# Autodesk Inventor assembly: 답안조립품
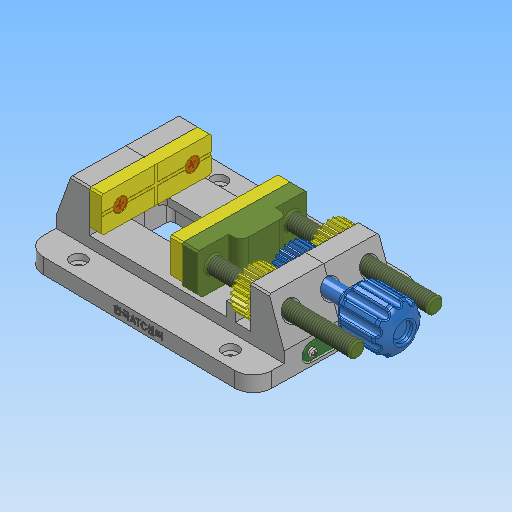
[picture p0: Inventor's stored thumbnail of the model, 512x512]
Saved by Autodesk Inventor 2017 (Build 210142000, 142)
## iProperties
Part Number: 답안조립품
Material: 일반
Document SubType Name: Assembly
Designer: user
Author: user
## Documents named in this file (10)
- C:\Users\user\Desktop\610306V1023\답안조립품.iam
- C:\Users\user\Desktop\610306V1023\바이스본체 A.ipt
- C:\Users\user\Desktop\610306V1023\바이스본체 B.ipt
- C:\Users\user\Desktop\610306V1023\고정 플레이트.ipt
- C:\Users\user\Desktop\610306V1023\십자오목머리나사 M3.ipt
- C:\Users\user\Desktop\610306V1023\십자접시머리나사 M4.ipt
- C:\Users\user\Desktop\610306V1023\지지대.ipt
- C:\Users\user\Desktop\610306V1023\슬라이딩 부품.ipt
- C:\Users\user\Desktop\610306V1023\스퍼기어.ipt
- C:\Users\user\Desktop\610306V1023\핸들.ipt
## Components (3 placed, 2 different names)
1. 고정 플레이트:1
2. 고정 플레이트:2
3. 핸들:1
